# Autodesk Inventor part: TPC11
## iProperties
Shininess: 64.0
Length Units: 11272
Angle Units: 11279
Time Units: 11290
Mass Units: 11286
Length Display Precision: 3
Angle Display Precision: 2
Compacted: True
Part Number: TPC11
Document SubType Name: Modeling
Created: 2004-08
Designer: Lori
Manufacturer: Standard
Standards Organization: Custom
Density: 0.0
Volumn: 0.0
Area: 0.0
PropertySet Name: Model Information
Control State: 0
Master: False
Checked Out: False
Author: Lori
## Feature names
1. Base1
